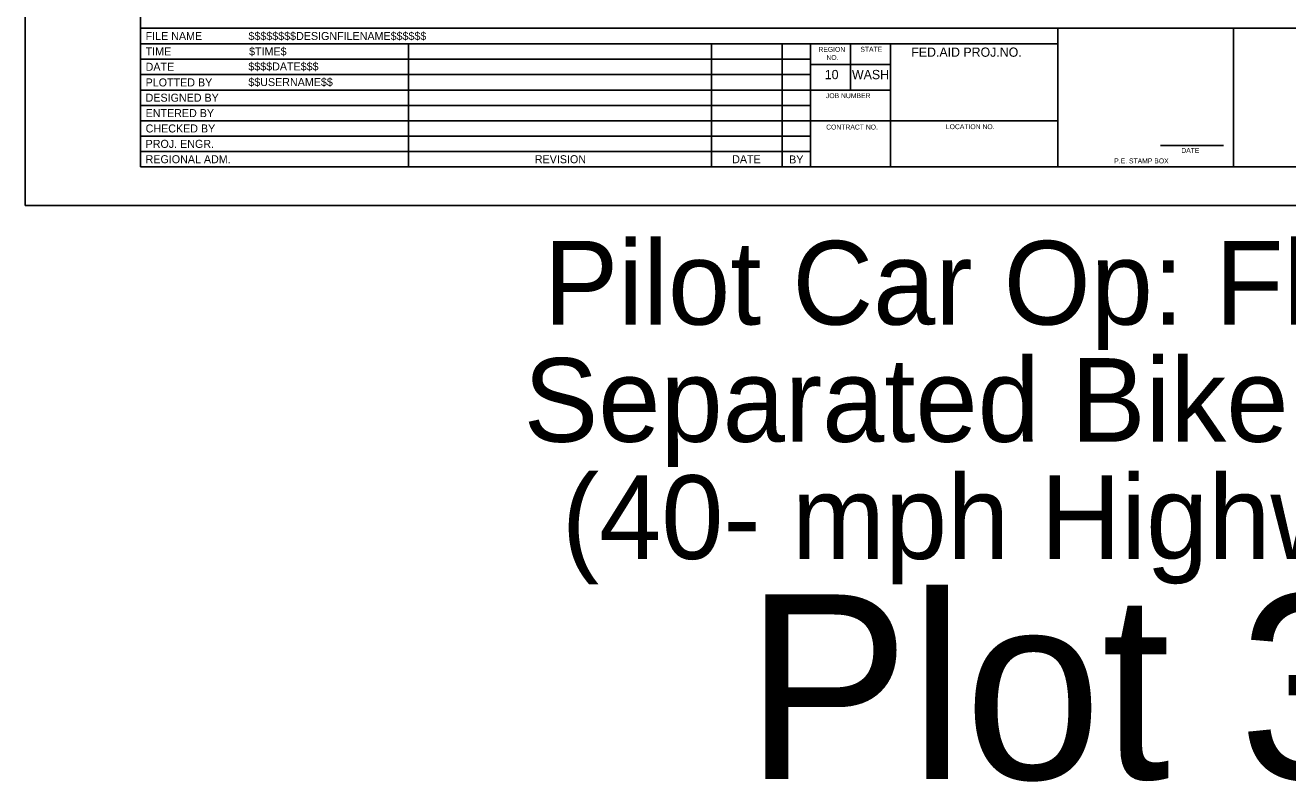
# Model space of a CAD drawing. Extents: x 99999.1 to 100095.7, y 99995 to 100010.7.
# Drawn here: x 100039.06 to 100049.33, y 99995.01 to 100001.15 of the extents above; entities that cross this region are included whole.
import ezdxf

# ---------------------------------------------------------------- set-up
doc = ezdxf.new("R2010")
doc.units = 0
for name, color, linetype in [('SH_GI_PlotLimits', 7, 'Continuous'), ('SH_GI_SheetBorder', 7, 'Continuous'), ('SH_GI_SheetLocationText', 7, 'Continuous'), ('SH_GI_SheetTextInCells', 7, 'Continuous'), ('SH_GI_TitleBlockText', 7, 'Continuous')]:
    doc.layers.add(name, color=color, linetype=linetype)

msp = doc.modelspace()

# ---------------------------------------------------------------- linework, layer by layer
at = {"layer": 'SH_GI_PlotLimits'}
msp.add_lwpolyline([(100039.062, 99999.687), (100056.062, 99999.687), (100056.062, 100010.687), (100039.062, 100010.687)], close=True, dxfattribs=at)
at = {"layer": 'SH_GI_SheetBorder'}
for p, q in [((100040, 100010.375), (100040, 100000)), ((100040, 100001.126), (100055.75, 100001.126)), ((100047.457, 100000), (100047.457, 100001.126)), ((100048.883, 100000), (100048.883, 100001.126)), ((100040, 100001.001), (100047.457, 100001.001)), ((100042.179, 100001.001), (100042.179, 100000)), ((100044.641, 100001.001), (100044.641, 100000)), ((100045.216, 100001.001), (100045.216, 100000)), ((100045.445, 100001.001), (100045.445, 100000)), ((100045.772, 100000.625), (100045.772, 100001.001)), ((100046.096, 100000), (100046.096, 100001.001)), ((100040, 100000.876), (100042.182, 100000.876)), ((100042.182, 100000.876), (100045.447, 100000.876)), ((100046.096, 100000.831), (100045.447, 100000.831)), ((100040, 100000.751), (100042.182, 100000.751)), ((100042.182, 100000.751), (100045.447, 100000.751)), ((100040, 100000.625), (100045.447, 100000.625)), ((100046.096, 100000.625), (100045.447, 100000.625)), ((100040, 100000.5), (100045.447, 100000.5)), ((100040, 100000.375), (100045.447, 100000.375)), ((100047.457, 100000.375), (100045.447, 100000.375)), ((100040, 100000.25), (100045.447, 100000.25)), ((100040, 100000.125), (100045.447, 100000.125)), ((100048.29, 100000.173), (100048.802, 100000.173)), ((100040, 100000), (100055.75, 100000))]:
    msp.add_line(p, q, dxfattribs=at)

# ---------------------------------------------------------------- texts
at = {"layer": 'SH_GI_SheetLocationText'}
for s, height, p in [('Pilot Car Op: Flagger', 0.68, (100043.277, 99998.719)), ('Separated Bike Lane', 0.68, (100043.114, 99997.767)), ('(40- mph Highways)', 0.68, (100043.424, 99996.815)), ('Plot 3', 1.5, (100044.913, 99995.027))]:
    msp.add_text(s, height=height, dxfattribs=at).set_placement(p)
at = {"layer": 'SH_GI_SheetTextInCells'}
for s, height, p in [('FILE NAME', 0.0651, (100040.041, 100001.031)), ('TIME', 0.0651, (100040.041, 100000.906)), ('REGION', 0.04, (100045.51, 100000.935)), ('STATE', 0.04, (100045.851, 100000.936)), ('FED.AID PROJ.NO.', 0.07506, (100046.265, 100000.895)), ('DATE', 0.0651, (100040.041, 100000.781)), ('NO.', 0.04, (100045.575, 100000.869)), ('PLOTTED BY', 0.0651, (100040.041, 100000.654)), ('10', 0.0751, (100045.562, 100000.713)), ('WASH', 0.0751, (100045.783, 100000.713)), ('DESIGNED BY', 0.06505, (100040.041, 100000.53)), ('JOB NUMBER', 0.04, (100045.571, 100000.559)), ('ENTERED BY', 0.0651, (100040.041, 100000.405)), ('CHECKED BY', 0.0651, (100040.041, 100000.28)), ('CONTRACT NO.', 0.04003, (100045.573, 100000.304)), ('LOCATION NO.', 0.04003, (100046.546, 100000.307)), ('PROJ. ENGR.', 0.06505, (100040.041, 100000.155)), ('REGIONAL ADM.', 0.06505, (100040.041, 100000.03)), ('REVISION', 0.0651, (100043.205, 100000.03)), ('DATE', 0.0651, (100044.809, 100000.03)), ('BY', 0.0651, (100045.272, 100000.028)), ('DATE', 0.04, (100048.46, 100000.114)), ('P.E. STAMP BOX', 0.04003, (100047.915, 100000.029))]:
    msp.add_text(s, height=height, dxfattribs=at).set_placement(p)
at = {"layer": 'SH_GI_TitleBlockText'}
for s, height, p in [('$$$$$$$$DESIGNFILENAME$$$$$$', 0.06505, (100040.877, 100001.031)), ('$TIME$', 0.0651, (100040.882, 100000.906)), ('$$$$DATE$$$', 0.06505, (100040.876, 100000.784)), ('$$USERNAME$$', 0.06505, (100040.876, 100000.657))]:
    msp.add_text(s, height=height, dxfattribs=at).set_placement(p)

doc.saveas('drawing.dxf')
